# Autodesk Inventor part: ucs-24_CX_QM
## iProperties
Shininess: 20.0
Length Units: 11269
Angle Units: 11279
Time Units: 11290
Mass Units: 11283
Length Display Precision: 2
Angle Display Precision: 2
Part Number: ucs-24_CX_QM
Material: nicht zugewiesen
Document SubType Name: Modellieren
Description: ucs-15/CX/QM
Checked By: Alves
Created: 2005-08
Designer: Ohle
Manufacturer: Standard
Standards Organization: Custom
Density: 0.0
Volumn: 0.0
Area: 0.0
PropertySet Name: Model Information
Control State: 0
Master: False
Checked Out: False
Last Check In By: ohle
Last Check In Date: 2005-08-25
BESTELLNUMMER: ucs-15/CX/QM
ME: ST
Title: ucs Sensoren
Author: Ohle
Comments: keine Bemerkung
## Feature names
1. Grundkörper [Extrusion]
2. Prismenschiene,unten [Extrusion]
3. Rundung 0,3_unten [Fillet]
4. Tastenfeld LED [Extrusion]
5. LED [Extrusion]
6. Taste [Extrusion]
7. Rundung GK1 [Fillet]
8. Rundung GK2 [Fillet]
9. Fase Taste1 [Chamfer]
10. Fase Taste2 [Chamfer]
11. Gewindeansatz [Revolution]
12. Kabelausgang [Extrusion]
13. Rundung KA1 [Fillet]
14. Rundung KA2 [Fillet]
15. Pole [Extrusion]
16. Rundung Pole [Fillet]
17. Verdrehsicherung [Extrusion]
18. Gewinde M4 [Hole]
19. Prismenschiene,seitlich [Extrusion]
20. Rundung 0,3_seitlich [Fillet]
21. Kerbe Gewindeansatz [Extrusion]
22. Drehung2 [Revolution]
23. Extrusion13
24. Extrusion14
25. Rundung8 [Fillet]
26. Rundung9 [Fillet]
27. Rundung10 [Fillet]
28. Extrusion15
29. Extrusion16
